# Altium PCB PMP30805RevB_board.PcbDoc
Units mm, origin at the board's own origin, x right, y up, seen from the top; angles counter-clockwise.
Board outline 68.58 x 25.4 mm, 2 copper layers (Top Layer, Bottom Layer), stack 1.575 mm thick; 47 components, 22 nets, 119 pads, 31 vias.
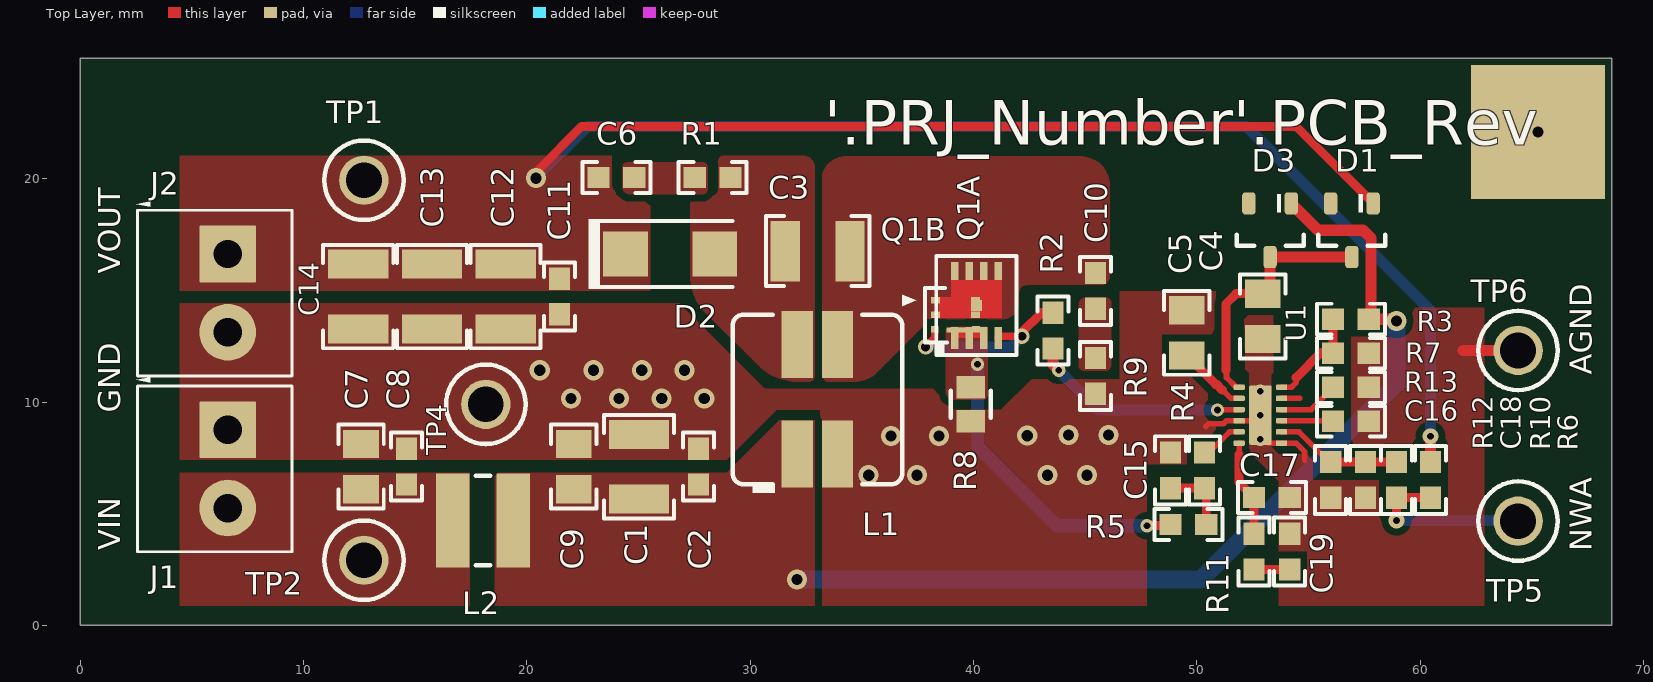
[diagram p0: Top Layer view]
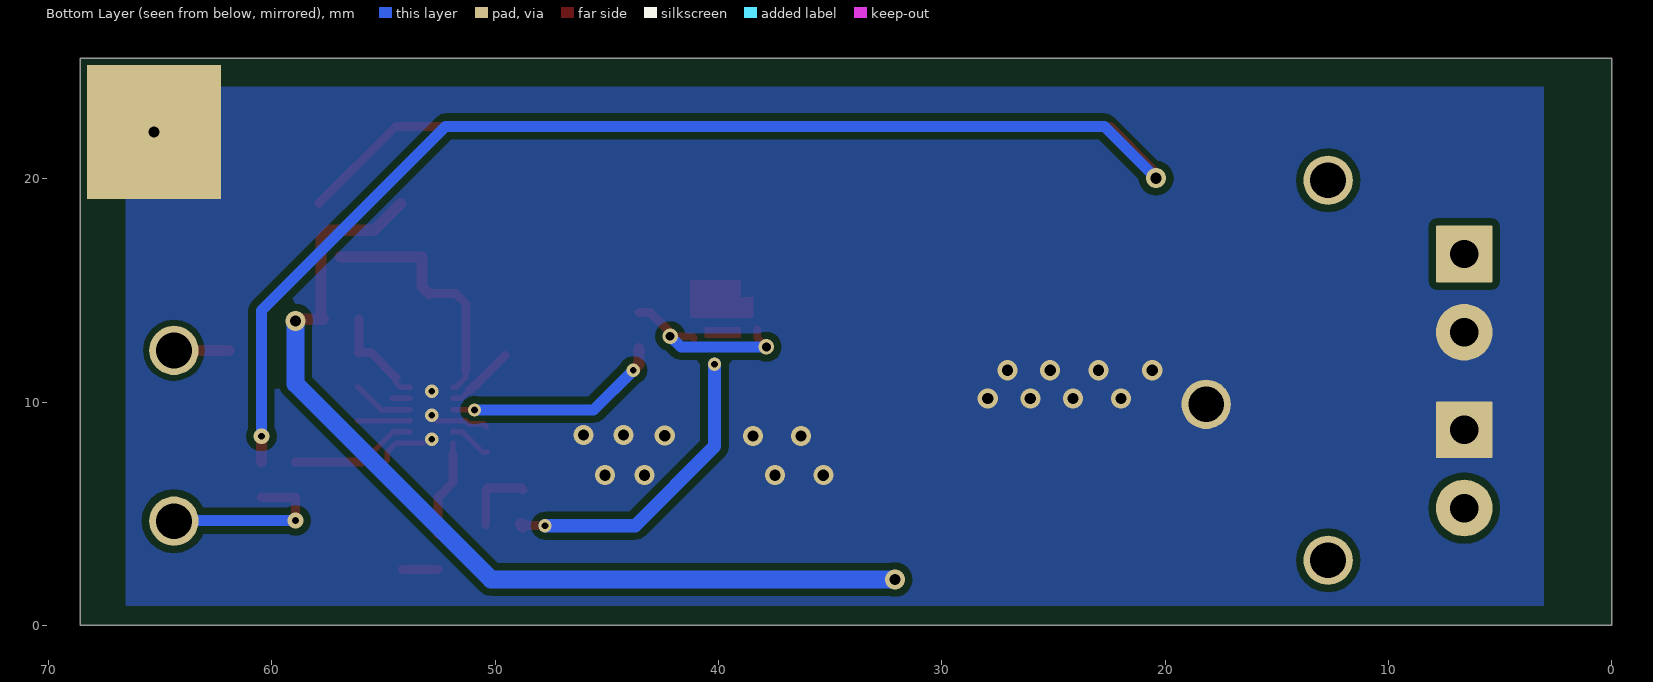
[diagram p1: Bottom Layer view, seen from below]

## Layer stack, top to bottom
Top Solder: solder mask 0.0102, Solder Resist, Dk 3.5
Top Layer: signal copper 0.0356
Dielectric1: core 1.5037, FR-4, Dk 4.8
Bottom Layer: signal copper 0.0356
Bottom Solder: solder mask 0.0102, Solder Resist, Dk 3.5

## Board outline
0,0 0,25.4 68.58,25.4 68.58,0

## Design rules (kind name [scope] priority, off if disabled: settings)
AcuteAngle [All] p1: minimum=4.50000000000000E+0001 checktracksonly=FALSE
AssemblyTestPointUsage [All] p1: valid=2
BoardOutlineClearance BoardOutlineClearance_MountingHoles [OnCopper and InComponentClass('Mounting Holes')] p1: gap=1 ignorepadtopadclearanceinfootprint=FALSE
BoardOutlineClearance BoardOutlineClearance_Poly [OnCopper and IsPoly] p2: gap=0.635 ignorepadtopadclearanceinfootprint=FALSE
BoardOutlineClearance [OnCopper and Not InComponentClass('Logo') and not InComponentClass('FiducialMark') and not InRegion(1000,500,4000,800) and not InPoly] p3: gap=1.905 ignorepadtopadclearanceinfootprint=FALSE
Clearance Clearance_Keepouts [((IsTrack Or IsArc) And Not InPoly) And IsFree and IsKeepOut vs ((IsTrack Or IsArc) And Not InPoly) And IsFree and IsKeepOut] p1: gap=0 ignorepadtopadclearanceinfootprint=FALSE
Clearance Clearance_Poly_1 [InPolygon vs InComponent('U1')] p2: gap=0.32 ignorepadtopadclearanceinfootprint=TRUE except(0.2: Arc-Fill Arc-Poly Arc-Region Track-Fill Track-Poly Track-Region SMDPad-Fill SMDPad-Poly SMDPad-Region Fill-Fill Fill-Poly Fill-Region Poly-Poly Poly-Region Region-Region)
Clearance Clearance_Poly [InPolygon] p3: gap=0.32 ignorepadtopadclearanceinfootprint=TRUE
Clearance Clearance_FiducialMark [IsKeepOut and InComponentClass('FiducialMark') vs IsPad and InComponentClass('FiducialMark')] p4: gap=0 ignorepadtopadclearanceinfootprint=FALSE
Clearance [All] p5: gap=0.2 ignorepadtopadclearanceinfootprint=TRUE
ComponentClearance ComponentClearance_MountingHoles_FiducialMarks [InComponentClass('Mounting Holes') vs InComponentClass('FiducialMark')] p1: gap=1.27 collisioncheckmode=3 verticalgap=0.254 showdistances=FALSE
ComponentClearance ComponentClearance_Shunt [InComponentClass('Header') vs InComponentClass('Shunt')] p2: gap=0 collisioncheckmode=3 verticalgap=0 showdistances=FALSE
ComponentClearance ComponentClearance_Logo [InComponentClass('Logo')] p3: gap=1.27 collisioncheckmode=3 verticalgap=0.254 showdistances=FALSE
ComponentClearance ComponentClearance_ScrewToNut [(HasFootprint('NY PMS 440 0025 PH')) vs (HasFootprint('Keystone_1902C'))] p4: gap=0.127 collisioncheckmode=3 verticalgap=0.254 showdistances=FALSE
ComponentClearance ComponentClearance_MountingHoles [InComponentClass('Mounting Holes')] p5: gap=6.35 collisioncheckmode=3 verticalgap=2540 showdistances=FALSE
ComponentClearance ComponentClearance_SmallPassives [HasFootprint('0201*') or HasFootprint('0402*') or HasFootprint('0508') or HasFootprint('0603*') or HasFootprint('0612') or HasFootprint('0805*') or HasFootprint('0815*') or HasFootprint('0830*') or HasFootprint('1206*') or HasFootprint('1210*') or HasFootprint('1808*') or HasFootprint('1812*') or HasFootprint('1825*') or HasFootprint('2010*') or HasFootprint('2220*') or HasFootprint('2225*') or HasFootprint('2512*') or HasFootprint('2728*') or HasFootprint('3518*') or HasFootprint('PG-TSDSON-8FL') vs HasFootprint('0201*') or HasFootprint('0402*') or HasFootprint('0508') or HasFootprint('0603*') or HasFootprint('0612') or HasFootprint('0805*') or HasFootprint('0815*') or HasFootprint('0830*') or HasFootprint('1206*') or HasFootprint('1210*') or HasFootprint('1808*') or HasFootprint('1812*') or HasFootprint('1825*') or HasFootprint('2010*') or HasFootprint('2220*') or HasFootprint('2225*') or HasFootprint('2512*') or HasFootprint('2728*') or HasFootprint('3518*') or HasFootprint('PG-TSDSON-8FL')] p6: gap=0.38 collisioncheckmode=3 verticalgap=0.254 showdistances=FALSE
ComponentClearance ComponentClearance_THtoSMT [IsThruComponent vs IsSMTComponent] p7: gap=1.016 collisioncheckmode=3 verticalgap=0.762 showdistances=FALSE
ComponentClearance ComponentClearance_THtoTH [IsThruComponent vs IsThruComponent] p8: gap=0.762 collisioncheckmode=3 verticalgap=0.762 showdistances=FALSE
ComponentClearance ComponentClearance_1 [InComponent('Q1A') vs InComponent('Q1B')] p9: gap=0 collisioncheckmode=3 verticalgap=0 showdistances=FALSE
ComponentClearance [All] p10: gap=0.762 collisioncheckmode=3 verticalgap=0.254 showdistances=FALSE
DiffPairsRouting [All] p1: maxlimit=2.54 minlimit=0.254 mostfreqgap=0.254 toplayer_minwidth=0.381 toplayer_maxwidth=0.381 toplayer_prefwidth=0.381 bottomlayer_minwidth=0.381 bottomlayer_maxwidth=0.381 bottomlayer_prefwidth=0.381 maxuncoupledlength=25.4
FabricationTestPointUsage TestPointUsage [All] p1: valid=2 allowmultiple=FALSE
FabricationTestpoint Testpoint [All] p1: side=3 testpointundercomponent=TRUE minsize=1.016 maxsize=2.54 preferedsize=1.524 minholesize=0 maxholesize=1.016 preferedholesize=0.813 testpointgrid=0.025 allowsidetop=TRUE allowsidebottom=TRUE usegrid=TRUE gridtolerance=0
FanoutControl Fanout_LCC [IsLCC] p1: bgadir=Out bgaviamode=Centered fanoutstyle=Auto fanoutdirection=Alternating viagrid=0.025 // Fanout_LCC (Default Rule)
FanoutControl Fanout_BGA [IsBGA] p2: bgadir=Out bgaviamode=Centered fanoutstyle=Auto fanoutdirection=Alternating viagrid=0.025 // Fanout_BGA (Default Rule)
FanoutControl Fanout_Default [All] p4: bgadir=Out bgaviamode=Centered fanoutstyle=Auto fanoutdirection=Alternating viagrid=0.025 // Fanout_Default (Default Rule)
FanoutControl Fanout_Small [(CompPinCount < 5)] p5: bgadir=Out bgaviamode=Centered fanoutstyle=Auto fanoutdirection=OutThenIn viagrid=0.025 // Fanout_Small (Default Rule)
HoleSize [All] p1: absolutevalues=TRUE maxlimit=6.375 minlimit=0.3 maxpercent=80.000 minpercent=20.000
MinimumAnnularRing MinimumAnnularRing_ThermalPadVias [IsVia and InAnyComponent] p1: minimumring=0.15
MinimumAnnularRing [All] p2: minimumring=0.2
MinimumSolderMaskSliver MinimumSolderMaskSliver_Logo [InComponentClass('Logo') vs InComponentClass('Logo')] p1: minsoldermaskwidth=0.018
MinimumSolderMaskSliver [All] p2: minsoldermaskwidth=0.1
PlaneConnect [All] p1: planeconnectstyle=Relief reliefexpansion=0.254 reliefentries=4 reliefconductorwidth=0.254 reliefairgap=0.254
PolygonConnect PolygonConnect_TP6 [InComponent('TP6')] p1: connectstyle=NoConnect reliefconductorwidth=0.254 reliefentries=4 polygonreliefangle="90 Angle" airgapwidth=0.254
PolygonConnect [All] p2: connectstyle=Direct reliefconductorwidth=0.254 reliefentries=4 polygonreliefangle="90 Angle" airgapwidth=0.254
RoutingVias ThermalPadVias [IsVia and InAnyComponent] p1: holewidth=0.2 width=0.5 viastyle="Through Hole" minholewidth=0.2 minwidth=0.5 maxholewidth=0.33 maxwidth=0.6
RoutingVias [All] p2: holewidth=0.5 width=0.9 viastyle="Through Hole" minholewidth=0.3 minwidth=0.6 maxholewidth=1.016 maxwidth=1.651
SilkToBoardRegionClearance [Not ((IsComment or IsDesignator) And (Hide <> 'False')) and not InRegion(1000,500,4000,800)] p1:
SilkToSilkClearance SilkToSilkClearance_Pb-FreeLogo [(HasFootprint('Pb-Free_Overlay_Medium') OR HasFootprint('Pb-Free_Overlay_Small')) vs (HasFootprint('Pb-Free_Overlay_Medium') OR HasFootprint('Pb-Free_Overlay_Small'))] p1: silktosilkclearance=0
SilkToSilkClearance [All] p2: silktosilkclearance=0.1
SilkToSolderMaskClearance SilkToComponentPadClearance [(IsPad or IsFill or IsRegion) and InAnycomponent] p1: minsilkscreentomaskgap=0.127 clearancetoexposedcopper=TRUE
SilkToSolderMaskClearance "Silk to Solder Mask Opening" [All] p2: minsilkscreentomaskgap=0.1 clearancetoexposedcopper=FALSE
SolderMaskExpansion [All] p1: expansion=0.05
UnRoutedNet [All] p1: checkbadconnections=TRUE
Width [All] p1: maxlimit=2.54 minlimit=0.152 preferedwidth=0.254 checkconnectedcopper=TRUE
14 further rules are at their usual default settings.

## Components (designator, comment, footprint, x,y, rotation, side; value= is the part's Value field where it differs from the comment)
C1 "GRM32ER71H106KA12L" 1210_270 25.019,7.112 r90 top value=10uF
C2 "GCM188R71H104KA57D" 0603 27.686,7.112 r90 top value=0.1uF
C3 "GRM32ER71H106KA12L" 1210_270 33.02,16.764 r0 top value=10uF
C4 "GRM21BR71H105KA12L" 0805_HV 52.959,13.843 r90 top value=1uF
C5 "GRM21BR71A105KA01L" 0805_HV 49.549,13.108 r90 top value=1uF
C6 "GCM1885C2A101JA16D" 0603 24.003,20.066 r180 top value=100pF
C7 "GRM21BR71H105KA12L" 0805_HV 12.573,7.112 r90 top value=1uF
C8 "GCM188R71H103KA37D" 0603 14.605,7.112 r90 top value=0.01uF
C9 "GRM21BR71H105KA12L" 0805_HV 22.098,7.112 r90 top value=1uF
C10 "GCM1885C2A101JA16D" 0603 45.466,14.986 r270 top value=100pF
C11 "GRM188R71E104KA01D" 0603 21.463,14.732 r270 top value=0.1uF
C12 "GRM32ER71E226KE15L" 1210_270 19.05,14.732 r270 top value=22uF
C13 "GRM32ER71E226KE15L" 1210_270 15.748,14.732 r270 top value=22uF
C14 "GRM32ER71E226KE15L" 1210_270 12.446,14.732 r270 top value=22uF
C15 "GRM188R71E102KA01D" 0603 48.824,6.951 r90 top value=1000pF
C16 "GRM188R71E104KA01D" 0603 56.896,9.144 r0 top value=0.1uF
C17 "GRM1885C1E561JA01D" 0603 53.358,5.733 r0 top value=560pF
C18 "GRM1885C1H220JA01D" 0603 57.554,6.524 r270 top value=22pF
C19 "GRM188R71E104KA01D" 0603 54.158,3.306 r90 top value=0.1uF
D1 "BAS16LT1G" SOT-23 56.945,17.7 r270 top value=100V
D2 "B360AM-13-F" SMA 26.416,16.637 r0 top value=60V
D3 "BAS16LT1G" SOT-23 53.281,17.7 r270 top value=100V
J1 "ED555/2DS" TERM_BLK_ED555-2DS 6.604,8.763 r270 top
J2 "ED555/2DS" TERM_BLK_ED555-2DS 6.604,16.637 r270 top
L1 "SRF0703-100M" SRF0703 33.009,10.123 r90 top value=10uH
L2 "SRN4012TA-R47M" SRN4012TA 18.034,4.699 r0 top value=470nH
Q1A "IAUZ18N10S5L420" PG-TSDSON-8FL 40.132,14.325 r90 top value=100V
Q1B "SQA442EJ-T1-GE3" PowerPAK_SC-70 39.192,13.894 r0 top value=60V
R1 "CRCW060310R0JNEAHP" 0603 28.321,20.066 r0 top value=10
R2 "ERJ-3GEY0R00V" 0603 43.561,13.208 r90 top value=0
R3 "CRCW0603261KFKEA" 0603 56.896,13.716 r0 top value=261k
R4 "ERJ-3GEY0R00V" 0603 50.348,6.951 r270 top value=0
R5 "CRCW0603100RFKEA" 0603 49.623,4.524 r180 top value=100
R6 "CRCW060349R9FKEA" 0603 60.468,6.524 r90 top value=49.9
R7 "CRCW060393K1FKEA" 0603 56.896,12.192 r180 top value=93.1k
R8 "WSLP0805R0300FEB" WSLP0805 39.878,9.906 r90 top value=0.03
R9 "CRCW060310R0JNEAHP" 0603 45.466,11.176 r90 top value=10
R10 "CRCW060360K4FKEA" 0603 58.944,6.524 r270 top value=60.4k
R11 "CRCW06033K32FKEA" 0603 52.558,3.306 r90 top value=3.32k
R12 "CRCW06035K49FKEA" 0603 55.995,6.524 r90 top value=5.49k
R13 "CRCW060310K0FKEA" 0603 56.896,10.668 r180 top value=10.0k
TP1 "5010" Keystone5010 12.7,19.939 r0 top
TP2 "5010" Keystone5010 12.7,2.921 r0 top
TP4 "5011" Keystone5011 18.161,9.906 r0 top
TP5 "5014" Keystone5014 64.389,4.674 r0 top
TP6 "5011" Keystone5011 64.389,12.319 r0 top
U1 "LM51551QDSSRQ1" DSS0012C 52.848,9.418 r0 top

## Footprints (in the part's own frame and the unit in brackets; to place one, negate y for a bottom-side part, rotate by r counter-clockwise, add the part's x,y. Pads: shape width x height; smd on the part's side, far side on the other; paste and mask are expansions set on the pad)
0603 [mm] "0603 from SM-752 data"
  rect 1x0.95 smd: 1(-0.8,0) 2(0.8,0)
  silkscreen extent -1.52,-0.69 1.52,0.69, body extent -0.87,-0.47 0.87,0.47, height 1
0805_HV [mil] "0805 with 30mil clearance between pads"
  rect 50x63 smd: 1(-40,0) 2(40,0)
  silkscreen extent -74,-40 74,40, body extent -43,-29 43,29, height 57
1210_270 [mm] "1210"
  rect 1.3x2.7 smd: 1(-1.45,0) 2(1.45,0)
  silkscreen extent -2.32,-1.57 2.32,1.57, body extent -1.7,-1.35 1.7,1.35, height 2.7
DSS0012C [mm] "WSON-12"
  rrect40% 0.5x0.25 smd: 1(-0.95,1.25) 2(-0.95,0.75) 3(-0.95,0.25) 4(-0.95,-0.25) 5(-0.95,-0.75) 6(-0.95,-1.25) 7(0.95,-1.25) 8(0.95,-0.75) 9(0.95,-0.25) 10(0.95,0.25) 11(0.95,0.75) 12(0.95,1.25)
  rrect11% 0.95x1.17 on Top Paste: 13(0,-0.685) 13(0,0.685)
  rrect11% 1x2.65 smd paste-0.5: 13(0,0)
  body extent -1,-1.5 1,1.5, height 0.81
Keystone5010 [mil] "Keystone Multipurpose loops"
  round 87 hole 63: 1(0,0)
  silkscreen extent -70,-70 70,70, body extent -63,-63 63,62, height 319
Keystone5011 [mil] "Keystone Multipurpose loops"
  round 87 hole 63: 1(0,0)
  silkscreen extent -70,-70 70,70, body extent -63,-63 63,62, height 319
Keystone5014 [mil] "Keystone Multipurpose loops"
  round 87 hole 63: 1(0,0)
  silkscreen extent -70,-70 70,70, body extent -63,-63 63,62, height 319
PG-TSDSON-8FL [mm] "SMD, 8-Leads, Body 3.3x3.3mm, Pitch 0.65mm"
  rect 1x0.34 smd: 1(-1.45,0.975) 2(-1.45,0.325) 3(-1.45,-0.325) 4(-1.45,-0.975)
  rect 0.8x0.34 smd: 5(1.55,-0.975) 6(1.55,-0.325) 7(1.55,0.325) 8(1.55,0.975)
  rect 0.5x0.5 smd: 9(0,0)
  Top Layer region: -0.56,-1.145 1.15,-1.145 1.15,1.145 -0.56,1.145
  Top Layer region: -0.95,1.15 -1.45,1.15 -1.45,-0.49 -0.95,-0.49
  silkscreen extent -2.22,-1.8 2.22,1.8, body extent -1.7,-1.7 1.7,1.7, height 1.11
PowerPAK_SC-70 [mm] "Vishay PowerPAK SC70-6L  document 73001 rev 06-Aug-07"
  rect 0.401x0.3 smd: 1(-0.9,0.666) 2(-0.9,0.016) 5(0.9,0.016) 6(0.9,0.666)
  rect 0.35x0.3 smd: 3(-0.925,-0.634) 4(0.925,-0.634)
  rect 0.87x0.235 smd: 7(0.04,-0.666)
  Top Layer region: 0.75,0.816 -0.75,0.816 -0.75,-0.134 0.75,-0.134
  silkscreen extent -2.39,-1.22 -0.38,1.22, body extent -1,-1 1.05,1.05, height 0.73
SMA [mm] "Molded Diode, 2-Leads, Body 4.3x2.6mm, IPC Medium Density, based on OnSemi component dimensions and land pattern"
  rect 2x2 smd: 1(-2,0) 2(2,0)
  silkscreen extent -3.66,-1.57 2.79,1.57, body extent -2.6,-1.3 2.6,1.3, height 2.42
SOT-23 [mm] "SOT23, 3-Leads, Body 2.9x1.3mm, Pitch 0.95mm, Lead Span 2.5mm, IPC Medium Density"
  rrect50% 1x0.6 smd: 1(-1.2,0.95) 2(-1.2,-0.95) 3(1.2,0)
  silkscreen extent -1.63,-1.5 0.7,1.5, body extent -1.16,-1.45 1.21,1.45, height 1
SRF0703 [mm] "SMD, 4-Leads, Body 7.6x7.6mm"
  rect 3x1.4 smd: 1(-2.45,0.9) 2(-2.45,-0.9) 3(2.45,-0.9) 4(2.45,0.9)
  silkscreen extent -4.2,-3.8 3.8,3.8, body extent -3.8,-3.8 3.8,3.8, height 3.41
SRN4012TA [mm] "SMD, 2-Leads, Body 4.2x4.2mm"
  rect 1.5x4.2 smd: 1(-1.35,0) 2(1.35,0)
  silkscreen extent -0.33,-2 0.33,2, body extent -1.99,-1.99 1.99,1.99, height 1.19
TERM_BLK_ED555-2DS [mil]
  rrect4% 100x100 hole 50: 1(0,0)
  round 100 hole 50: 2(138,0)
  silkscreen extent -93,-161 215,113, body extent -69,-150 207,106, height 323
WSLP0805 [mm] "Vishay"
  rect 1.02x1.27 smd: 1(-0.76,0) 2(0.76,0)
  silkscreen extent -0.6,-0.9 0.6,0.9, body extent -1.14,-0.76 1.14,0.76, height 0.64

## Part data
C1 C3: library part CMP-0009226-3, "CAP, CERM, 10 uF, 50 V, +/- 10%, X7R, 1210", Cap_Case=1210, Manufacturer=MuRata, Supplier Part Number 1=490-6544-1-ND, TempCo=X7R, Tolerance_%=10%, Value1=Unknown, Value2=50V, ValueDisplayed=10uF
C2: "CAP, CERM, 0.1 µF, 50 V,+/- 10%, X7R, 0603", Cap_Case=0603, Manufacturer=MuRata, Supplier Part Number 1=490-4779-1-ND, TempCo=X7R, Tolerance_%=10, Value1="0.02 ohm", Value2=50V, ValueDisplayed=0.1µF
C4: library part CMP-0008350-2, "CAP, CERM, 1 uF, 50 V, +/- 10%, X7R, 0805", Cap_Case=0805, Manufacturer=MuRata, Supplier Part Number 1=490-4736-1-ND, TempCo=X7R, Tolerance_%=10%, Value1=Unknown, Value2=50V, ValueDisplayed=1uF
C5: library part CMP-0008313-2, "CAP, CERM, 1 uF, 10 V, +/- 10%, X7R, 0805", Cap_Case=0805, Manufacturer=MuRata, Supplier Part Number 1=490-1695-1-ND, TempCo=X7R, Tolerance_%=10%, Value1="0.007 ohm", Value2=10V, ValueDisplayed=1uF
C6 C10: "CAP, CERM, 100 pF, 100 V,+/- 5%, C0G/NP0, AEC-Q200 Grade 1, 0603", Cap_Case=0603, Manufacturer=MuRata, Supplier Part Number 1=490-4771-1-ND, TempCo=C0G/NP0, Tolerance_%=5, Value2=100V, ValueDisplayed=100pF
C7 C9: "CAP, CERM, 1 µF, 50 V,+/- 10%, X7R, 0805", Cap_Case=0805, Manufacturer=MuRata, Supplier Part Number 1=490-4736-1-ND, TempCo=X7R, Tolerance_%=10, Value2=50V, ValueDisplayed=1µF
C8: "CAP, CERM, 0.01 µF, 50 V,+/- 10%, X7R, AEC-Q200 Grade 1, 0603", Cap_Case=0603, Manufacturer=MuRata, Supplier Part Number 1=490-4778-1-ND, TempCo=X7R, Tolerance_%=10, Value2=50V, ValueDisplayed=0.01µF
C11 C16 C19: "CAP, CERM, 0.1 µF, 25 V,+/- 10%, X7R, 0603", Cap_Case=0603, Manufacturer=MuRata, Supplier Part Number 1=490-1524-1-ND, TempCo=X7R, Tolerance_%=10, Value2=25V, ValueDisplayed=0.1µF
C12 C13 C14: "CAP, CERM, 22 µF, 25 V,+/- 10%, X7R, 1210", Cap_Case=1210, Manufacturer=MuRata, Supplier Part Number 1=490-5313-1-ND, TempCo=X7R, Tolerance_%=10, Value1="0.002334 ohm", Value2=25V, ValueDisplayed=22µF
C15: "CAP, CERM, 1000 pF, 25 V,+/- 10%, X7R, 0603", Cap_Case=0603, Manufacturer=MuRata, Supplier Part Number 1=GRM188R71E102KA01D-ND, TempCo=X7R, Tolerance_%=10, Value2=25V, ValueDisplayed=1000pF
C17: "CAP, CERM, 560 pF, 25 V,+/- 5%, C0G/NP0, 0603", Cap_Case=0603, Manufacturer=MuRata, Supplier Part Number 1=GRM1885C1E561JA01D-ND, TempCo=C0G/NP0, Tolerance_%=5, Value2=25V, ValueDisplayed=560pF
C18: "CAP, CERM, 22 pF, 50 V,+/- 5%, C0G/NP0, 0603", Cap_Case=0603, Manufacturer=MuRata, Supplier Part Number 1=490-1411-1-ND, TempCo=C0G/NP0, Tolerance_%=5, Value2=50V, ValueDisplayed=22pF
D1 D3: library part CMP-0029193-2, "Diode, Switching, 100 V, 0.2 A, SOT-23", Manufacturer="ON Semiconductor", Value1=0.2A, Value2=1.25V
D2: "Diode, Schottky, 60 V, 3 A, AEC-Q101, SMA", Manufacturer="Diodes Inc.", Supplier Part Number 1=B360AM-13-FDICT-ND, Value1=3A, Value2=0.7V
J1 J2: library part CMP-0074913-1, "Terminal Block, 3.5mm Pitch, 2x1, TH", Color=Grey, Current_A=6A, Manufacturer="On-Shore Technology", Supplier Part Number 1=ED1514-ND, Voltage_V=150V
L1: "Coupled inductor, 10 µH, 2.47 A, 0.1652 ohm, SMD", Manufacturer=Bourns, Supplier Part Number 1=SRF0703-100MCT-ND, ValueDisplayed=10µH
L2: "Inductor, Shielded, Ferrite, 470 nH, 3.2 A, 0.03 ohm, AEC-Q200 Grade 1, SMD", Manufacturer=Bourns, Supplier Part Number 1=SRN4012TA-R47MCT-ND, Value1="0.03 ohm", Value2=3.2A, ValueDisplayed=470nH
Q1A: library part BSZ013NE2LS5IATMA1, "MOSFET, N-CH, 100 V, 40 A, 8-PG-TSDSON", Alternate Manufacturer=None, Manufacturer="Infineon Technologies", Value1="0.055 ohm", Value2="5.4 nC"
Q1B: library part CMP-0000233-1, "MOSFET, N-CH, 20 V, 7.8 A, AEC-Q101, PowerPAK SC-70", Alternate Manufacturer=None, Manufacturer=Vishay-Siliconix, PartNumber=SQA442EJ-T1_GE3, Supplier Part Number 1=SQA442EJ-T1_GE3CT-ND, Value1=0.032, Value2="9.7 nC"
R1 R9: "RES, 10, 5%, 0.25 W, 0603", Manufacturer=Vishay-Dale, Power_W=0.25, Supplier Part Number 1=541-10SACT-ND, TempCo="200 ppm/C", Tolerance_%=5, Value1=5%, Value2=0.25W, Value_Code=10R0, ValueDisplayed=10
R2 R4: library part CMP-0025874-4, "RES, 0, 5%, 0.1 W, AEC-Q200 Grade 0, 0603", Manufacturer=Panasonic, Power_W=100mW, Supplier Part Number 1=P0.0GCT-ND, TempCo="600 ppm/C", Tolerance_%=5%, Value2=0.1W, Value_Code=0000, ValueDisplayed=0
R3: library part CMP-0022244-4, "RES, 261 k, 1%, 0.1 W, AEC-Q200 Grade 0, 0603", Manufacturer=Vishay-Dale, Power_W=100mW, Supplier Part Number 1=541-261KHCT-ND, TempCo="100 ppm/C", Tolerance_%=1%, Value2=0.1W, Value_Code=261k
R5: library part CMP-0021991-2, "RES, 100, 1%, 0.1 W, 0603", Manufacturer=Vishay-Dale, Power_W=100mW, Supplier Part Number 1=541-100HCT-ND, TempCo="100 ppm/C", Tolerance_%=1%, Value2=0.1W, Value_Code=100R, ValueDisplayed=100
R6: library part CMP-0022448-4, "RES, 49.9, 1%, 0.1 W, AEC-Q200 Grade 0, 0603", Manufacturer=Vishay-Dale, Power_W=100mW, Supplier Part Number 1=541-49.9HCT-ND, TempCo="100 ppm/C", Tolerance_%=1%, Value2=0.1W, Value_Code=49R9, ValueDisplayed=49.9
R7: library part CMP-0022655-4, "RES, 93.1 k, 1%, 0.1 W, AEC-Q200 Grade 0, 0603", Manufacturer=Vishay-Dale, Power_W=100mW, Supplier Part Number 1=541-93.1KHCT-ND, TempCo="100 ppm/C", Tolerance_%=1%, Value2=0.1W, Value_Code=93k1, ValueDisplayed=93.1k
R8: "RES, 0.03, 1%, 0.5 W, 0805", Manufacturer=Vishay-Dale, Power_W=0.5, Supplier Part Number 1=WSLPB-.03CT-ND, TempCo="75 ppm/C", Tolerance_%=1, Value1=1%, Value2=0.5W, Value_Code=R030, ValueDisplayed=0.03
R10: library part CMP-0022532-4, "RES, 60.4 k, 1%, 0.1 W, AEC-Q200 Grade 0, 0603", Manufacturer=Vishay-Dale, Power_W=100mW, Supplier Part Number 1=541-60.4KHCT-ND, TempCo="100 ppm/C", Tolerance_%=1%, Value2=0.1W, Value_Code=60k4, ValueDisplayed=60.4k
R11: "RES, 3.32 k, 1%, 0.1 W, 0603", Manufacturer=Vishay-Dale, Power_W=0.1, Supplier Part Number 1=541-3.32KHCT-ND, TempCo="100 ppm/C", Tolerance_%=1, Value1=1%, Value2=0.1W, Value_Code=3k32, ValueDisplayed=3.32k
R12: library part CMP-0022512-4, "RES, 5.49 k, 1%, 0.1 W, AEC-Q200 Grade 0, 0603", Manufacturer=Vishay-Dale, Power_W=100mW, Supplier Part Number 1=541-5.49KHCT-ND, TempCo="100 ppm/C", Tolerance_%=1%, Value2=0.1W, Value_Code=5k49, ValueDisplayed=5.49k
R13: "RES, 10.0 k, 1%, 0.1 W, 0603", Manufacturer=Vishay-Dale, Power_W=0.1, Supplier Part Number 1=541-10.0KHCT-ND, TempCo="100 ppm/C", Tolerance_%=1, Value1=1%, Value2=0.1W, Value_Code=10k0, ValueDisplayed=10.0k
TP1 TP2: library part CMP-0055147-1, "Test Point, Multipurpose, Red, TH", Color=Red, Manufacturer=Keystone, Supplier Part Number 1=36-5010-ND
TP4 TP6: library part CMP-0055148-1, "Test Point, Multipurpose, Black, TH", Color=Black, Manufacturer=Keystone, Supplier Part Number 1=36-5011-ND
TP5: library part CMP-0055151-1, "Test Point, Multipurpose, Yellow, TH", Color=Yellow, Manufacturer=Keystone, Supplier Part Number 1=36-5014-ND
U1: library part CMP-0081541-1, "Automotive Grade 2.2-MHz Wide Input Non-synchronous Boost Controller, DSS0012C (WSON-12)", Alternate Manufacturer="Texas Instruments", Alternate PartNumber=LM51551QDSSTQ1

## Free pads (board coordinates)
  rect 6x6 hole 0.5: 7(65.278,22.098)

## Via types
v1: diameter 0.9, hole 0.5, Top Layer to Bottom Layer, 17 vias
v2: diameter 0.6, hole 0.3, Top Layer to Bottom Layer, 6 vias
v3: diameter 0.9, hole 0.5, Top Layer to Bottom Layer, tented top, 3 vias
v4: diameter 0.7, hole 0.4, Top Layer to Bottom Layer, 2 vias
v5: diameter 0.7, hole 0.3, Top Layer to Bottom Layer, tented top, 2 vias
v6: diameter 0.6, hole 0.3, Top Layer to Bottom Layer, tented top, 1 vias

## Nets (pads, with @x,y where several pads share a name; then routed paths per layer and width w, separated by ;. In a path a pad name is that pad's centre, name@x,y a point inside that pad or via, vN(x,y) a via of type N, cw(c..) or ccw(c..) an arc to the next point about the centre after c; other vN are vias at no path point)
AGND: C1.2 C2.2 C4.1 C5.2 C7.2 C8.2 C9.2 C11.2 C12.2 C13.2 C14.2 C15.2 C16.2 C17.2 C18.2 C19.2 J1.1 J2.2 L1.2 pad.7 R7.1 R8.1 R9.1 R12.1 R13.1 TP4.1 TP6.1 U1.4 U1.7 U1.13@52.848,9.418 | length 7.3
  Top Layer w0.25: 50.394,8.906 50.515,9.027 51.186,9.027 51.327,9.168 U1.4 52.598,9.168 v2(52.848,9.418) ; U1.13@53.213,8.168 U1.7 54.447,8.168 54.827,7.787 54.827,7.41
  Top Layer w0.5: 61.935,12.319 TP6.1
  other v1: 37.465,6.731 43.307,6.731 45.085,6.731 38.461,8.481 42.406,8.501 44.252,8.534 46.051,8.534 21.971,10.16 24.13,10.16 26.035,10.16 27.94,10.16 20.574,11.43 22.987,11.43 25.146,11.43 27.051,11.43
  other v2: 52.848,8.343 52.848,10.493
  other v3: 35.306,6.731 36.309,8.481
NetC3_1: C3.1 D2.2 L1.4 R1.2
NetC3_2: C3.2 C10.1 L1.3 Q1A.5 Q1A.6 Q1A.7 Q1A.8 Q1A.9 Q1B.1 Q1B.2 Q1B.5 Q1B.6
NetC4_2: C4.2 D1.3 D3.3 U1.1 | length 11.3
  Top Layer w0.25: 51.308,11.43 51.329,11.409 51.329,11.104 51.765,10.668 U1.1
  Top Layer w0.4: 51.308,11.43 51.308,14.402 51.765,14.859 C4.2
  Top Layer w0.5: C4.2 53.281,15.181 D3.3 D1.3
NetC5_1: C5.1 U1.2 | length 3.1
  Top Layer w0.25: 51.148,10.543 51.523,10.168 U1.2
  Top Layer w0.4: C5.1 50.846,10.795 50.896,10.795 51.148,10.543
NetC6_1: C6.1 R1.1
NetC7_1: C7.1 C8.1 J1.2 L2.1 TP2.1
NetC10_2: C10.2 R9.2
NetC15_1: C15.1 R4.2 R5.1 | length 3.3
  Top Layer w0.4: C15.1@48.749,6.076 C15.1 R4.2 50.423,6.076 R5.1
NetC16_1: C16.1 U1.9 | length 2.3
  Top Layer w0.25: U1.9 C16.1@56.145,9.168
NetC17_1: C17.1 R11.2 U1.6 | length 4.3
  Top Layer w0.25: 51.898,7.662 U1.6
  Top Layer w0.4: 51.898,7.662 51.898,6.393 C17.1 R11.2
NetC19_1: C19.1 R11.1 | length 1.6
  Top Layer w0.4: R11.1 C19.1
NetQ1A_1: Q1A.1 Q1A.2 Q1A.3 Q1B.4 Q1B.7 R5.2 R8.2 | length 13.8
  Top Layer w0.4: v2(47.768,4.47) R5.2@48.769,4.47
  Top Layer w0.6: R5.2@48.769,4.47 R5.2
  Bottom Layer w0.6: v2(40.178,11.693) 40.178,8.02 43.728,4.47 v2(47.768,4.47)
NetQ1A_4: Q1A.4 Q1B.3 R2.2 | length 8.5
  Top Layer w0.34: v4(37.855,12.476) 38.267,12.888 Q1B.3 ; Q1A.4 41.186,12.954 v4(42.164,12.954)
  Top Layer w0.4: v4(42.164,12.954) 42.164,13.122 43.05,14.008 R2.2
  Bottom Layer w0.5: v4(37.855,12.476) 41.686,12.476 v4(42.164,12.954)
NetR2_1: R2.1 U1.3 | length 9.9
  Top Layer w0.25: v6(50.927,9.652) 50.943,9.668 U1.3
  Top Layer w0.5: R2.1 43.561,11.684 v2(43.815,11.43) v2@43.777,11.43
  Bottom Layer w0.5: v2(43.815,11.43) 45.593,9.652 v6(50.927,9.652)
NetR3_1: R3.1 R7.2 U1.12 | length 4.7
  Top Layer w0.25: U1.12 54.234,10.668 54.447,10.881 54.447,11.104
  Top Layer w0.4: 54.447,11.104 55.577,12.234 R7.2@56.096,12.234 ; R7.2 R7.2@56.096,12.234 ; R3.1 R7.2@56.096,12.234 ; R7.2@56.145,12.234 R7.2@56.096,12.234
NetR4_1: R4.1 U1.5 | length 1.9
  Top Layer w0.25: R4.1 50.546,7.751 51.463,8.668 U1.5
NetR6_1: R6.1 R10.2 TP5.1 | length 8
  Top Layer w0.4: v5(58.944,4.699) R10.2 R6.1
  Bottom Layer w0.5: v5(58.944,4.699) TP5.1@64.389,4.699
NetR13_2: R13.2 U1.10 | length 2.8
  Top Layer w0.25: U1.10 55.12,9.668 56.12,10.668 R13.2@56.145,10.668
VFB: C18.1 R10.1 R12.2 U1.8 | length 5.7
  Top Layer w0.25: U1.8 54.583,8.668 55.927,7.324 R12.2
  Top Layer w0.4: R12.2 C18.1 R10.1
VIN: C1.1 C2.1 C9.1 D3.1 L1.1 L2.2 R3.2 | length 42.4
  Top Layer w0.5: D3.1 55.431,17.7 57.445,17.7 57.795,17.35 R3.2@57.795,13.772 ; R3.2 58.864,13.716 v3(58.944,13.637)
  Bottom Layer w0.8: v1(32.099,2.057) 32.099,2.061 50.182,2.061 58.944,10.823 v3(58.944,13.637)
VOUT: C6.2 C11.1 C12.1 C13.1 C14.1 D1.1 D2.1 J2.1 R6.2 TP1.1 | length 94.5
  Top Layer w0.4: v1@20.512,20.398 22.466,22.352 54.407,22.352 ; 54.443,22.352 D1.1
  Top Layer w0.5: R6.2 v5(60.468,8.481)
  Bottom Layer w0.5: v1(20.4,20.032) 22.72,22.352 ; 26.416,22.352 22.72,22.352 ; 52.172,22.352 22.72,22.352 ; 52.218,22.352 60.468,14.102 v5(60.468,8.481)
pads on no net: D1.2 D3.2 U1.11 U1.13@52.848,8.733 U1.13@52.848,10.103
copper on no net: | length 0.8
  Top Layer w0.25: 53.798,10.168 54.618,10.168

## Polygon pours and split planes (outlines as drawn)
NetC6_1 on Top Layer "TOP_LAYER_NETC6_1_P003" (solid, remove dead copper, pour order 3): 28.089,19.554 28.089,20.51 ccw(c27.844,20.51) 27.844,20.754 24.521,20.754 ccw(c24.521,20.504) 24.271,20.504 24.271,19.659 ccw(c24.626,19.659) 24.626,19.304 27.839,19.304 ccw(c27.839,19.554)
NetC10_2 on Top Layer "TOP_LAYER_NETC10_2_P001" (solid, remove dead copper, pour order 1): 46.158,13.691 46.158,14.472 ccw(c45.949,14.472) 45.949,14.681 45.009,14.681 ccw(c45.009,14.376) 44.704,14.376 44.708,14.224 44.708,11.638 ccw(c44.934,11.638) 44.934,11.412 45.908,11.412 ccw(c45.908,11.662) 46.158,11.662
AGND on Top Layer "TOP_LAYER_AGND_P016" (solid, remove dead copper, pour order 16): 52.349,8.915 52.349,7.786 53.677,6.458 53.677,0.889 62.865,0.889 62.865,14.224 56.442,14.224 54.731,12.513 54.731,9.256 54.381,8.906
AGND on Top Layer "TOP_LAYER_AGND_P014" (solid, remove dead copper, pour order 14): 42.605,11.035 46.544,11.035 46.544,14.967 50.846,14.967 50.846,7.214 39.53,7.214 39.157,7.587 39.157,9.376 39.433,9.652 41.222,9.652
AGND on Top Layer "TOP_LAYER_AGND_P013" (solid, remove dead copper, pour order 13): 4.445,14.425 26.814,14.425 30.646,10.593 38.191,10.593 39.116,9.668 47.768,9.668 47.768,0.889 33.147,0.889 33.147,9.668 31.196,9.668 28.954,7.426 4.445,7.426
AGND on Top Layer "TOP_LAYER_AGND_P010" (solid, remove dead copper, pour order 10): 52.131,13.975 53.423,13.975 53.423,11.31 53.34,11.227 53.34,9.779 52.349,9.779 52.349,11.303 52.172,11.481 52.172,11.938
NetQ1A_1 on Top Layer "TOP_LAYER_NETQ1A_1_P009" (solid, remove dead copper, pour order 9): 40.622,13.375 38.9,13.375 ccw(c38.9,13.238) 38.763,13.238 38.763,10.456 ccw(c39.116,10.456) 39.116,10.103 40.4,10.103 ccw(c40.4,10.343) 40.64,10.343 40.64,13.357 ccw(c40.622,13.357)
NetC3_2 on Top Layer "TOP_LAYER_NETC3_2_P007" (solid, remove dead copper, pour order 7): 46.101,19.7 ccw(c44.793,19.7) 44.793,21.008 34.296,21.008 ccw(c34.296,19.902) 33.19,19.902 33.19,17.298 ccw(c33.204,17.285) 33.19,17.272 33.19,11.115 ccw(c33.384,11.115) 33.384,10.922 34.717,10.922 ccw(c34.717,12.223) 35.637,11.303 37.744,13.411 cw(c38.481,12.674) 38.481,13.716 41.273,13.716 ccw(c41.273,14.506) 41.832,13.947 ccw(c41.337,14.442) 42.037,14.442 42.037,14.901 cw(c42.376,14.901) 42.376,15.24 45.72,15.24 ccw(c45.72,15.621) 46.101,15.621
NetC3_1 on Top Layer "TOP_LAYER_NETC3_1_P006" (solid, remove dead copper, pour order 6): 27.305,18.8 cw(c27.739,18.8) 27.739,19.233 28.25,19.233 ccw(c28.25,19.558) 28.575,19.558 28.575,20.824 cw(c28.796,20.824) 28.796,21.045 32.354,21.045 cw(c32.354,20.51) 32.889,20.51 32.889,11.164 cw(c32.647,11.164) 32.647,10.922 32.127,10.922 cw(c32.127,13.462) 30.331,11.666 28.049,13.947 cw(c29.845,15.743) 27.305,15.743
VOUT on Top Layer "TOP_LAYER_VOUT_P005" (solid, remove dead copper, pour order 5): 25.519,17.35 25.519,18.804 ccw(c25.146,18.804) 25.146,19.177 24.511,19.177 cw(c24.441,19.812) 23.806,19.742 23.806,21.045 4.445,21.045 4.445,14.986 25.519,14.986
VIN on Top Layer "TOP_LAYER_VIN_P004" (solid, remove dead copper, pour order 4): 18.55,6.848 18.55,0.889 32.893,0.889 32.893,9.185 31.306,9.185 28.956,6.835
NetC7_1 on Top Layer "TOP_LAYER_NETC7_1_P002" (solid, remove dead copper, pour order 2): 4.445,6.835 4.445,0.889 17.45,0.889 17.45,6.835
AGND on Bottom Layer "BOTTOM_LAYER_AGND_P030" (solid, remove dead copper, pour order 30): 3.048,0.889 66.548,0.889 66.548,24.13 3.048,24.13

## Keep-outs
Keep-Out Layer:
  text ".Layer_Name" at 14.656,-23.076 h1.52

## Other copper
Top Layer:
  pour cut-out: 53.619,8.306 53.34,8.306 53.34,8.534
  pour cut-out: 53.287,8.052 53.677,7.662 54.611,7.662 54.221,8.052
  text ".Layer_Name" at 14.656,-23.076 h1.52
Bottom Layer:
  text ".Layer_Name" at 14.656,-23.076 h1.52

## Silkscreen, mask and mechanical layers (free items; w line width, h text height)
Top Overlay:
  text "'.PRJ_Number'.PCB_Rev" at 33.316,21.526 h2
  text "VOUT" at 1.778,15.748 h1 r90
  text "AGND" at 67.691,11.219 h1 r90
  text "GND" at 1.778,9.525 h1 r90
  text "VIN" at 1.778,3.378 h1 r90
  text "NWA" at 67.691,3.326 h1 r90
  text ".Layer_Name" at 14.656,-23.076 h1.52
Bottom Overlay:
  text ".Layer_Name" at 14.656,-23.076 h1.52
Top Paste:
  text ".Layer_Name" at 14.656,-23.076 h1.52
Bottom Paste:
  text ".Layer_Name" at 14.656,-23.076 h1.52
Top Solder:
  text ".Layer_Name" at 14.656,-23.076 h1.52
  text ".Layer_Name" at 14.656,-23.076 h1.52
Bottom Solder:
  text "'.PRJ_Number'.PCB_Rev" at 28.051,15.451 h2
  text ".Layer_Name" at 14.656,-23.076 h1.52
Drill Guide:
  text ".Layer_Name" at 14.656,-23.076 h1.52
M1 Board Outline:
  the board outline again, w0.254
  text ".Layer_Name" at 14.656,-23.076 h1.52
M2 Board Dimensions:
  rectangle: 0,-8.255 3.175,-5.08
  rectangle: 3.175,-11.43 12.7,-8.255
  lines w0.178: 0,-8.255 25.4,-8.255 ; 3.175,-11.43 3.175,-5.08 ; 6.35,-11.43 6.35,-5.08 ; 12.7,-11.43 12.7,-5.08 ; 19.05,-11.43 19.05,-5.08 ; 0,-11.43 25.4,-11.43 25.4,-5.08 0,-5.08 0,-11.43
  text "'.Print_Date' '.Print_Time'" at 1.778,26.67 h1.5
  text ".Layer_Name" at 14.656,-23.076 h1.52
M3 3D STEP Top:
  text ".Layer_Name" at 14.656,-23.076 h1.52
M4 3D STEP Bottom:
  text ".Layer_Name" at 14.656,-23.076 h1.52
M5 Assembly Top:
  lines w0.254: -7.417,-24.896 160.223,-24.896 ; -7.417,-19.732 160.274,-19.732 ; -7.417,-14.567 -7.417,-30.061 94.31,-30.061 160.274,-30.061 160.274,-14.567 -7.404,-14.567 -7.404,-30.061 32.614,-30.061 ; 55.194,-30.061 55.194,-14.567 ; 87.376,-19.732 87.376,-14.567 ; 108.712,-19.732 108.712,-14.567 ; 124.511,-30.226 124.511,-25.074
  text "COMPONENTS MARKED 'DNP' SHOULD NOT BE POPULATED." at 29.299,-9.36 h1.52
  text "ASSEMBLY VARIANT:" at 29.286,-12.294 h1.52
  text ".VariantName" at 55.601,-12.294 h1.52
  text "PCB VIEWED FROM TOP SIDE" at -5.804,-17.924 h1.52
  text "BOARD #:" at 57.099,-17.924 h1.52
  text ".PRJ_Number" at 70.955,-17.924 h1.52
  text "REV:" at 92.405,-17.924 h1.52
  text ".PCB_Rev" at 99.809,-17.924 h1.52
  text "SVN REV:" at 113.69,-17.924 h1.52
  text ".VersionControl_RevNumber" at 126.543,-17.924 h1.52
  text "TID #:" at 57.099,-23.089 h1.52
  text ".TID" at 70.955,-23.089 h1.52
  text "PLOT NAME =" at -5.804,-28.304 h1.52
  text ".plot_File_Name" at 14.656,-28.304 h1.52
  text "GENERATED    :" at 57.15,-28.304 h1.52
  text ".Print_Date" at 79.235,-28.304 h1.52
  text ".Print_Time" at 97.752,-28.304 h1.52
  text "TEXAS INSTRUMENTS" at 129.87,-28.304 h1.52
M6 Assembly Bottom:
  lines w0.254: -7.429,-19.744 160.261,-19.744 ; -7.379,-24.909 160.261,-24.909 ; 28.334,-30.239 28.334,-25.087 ; 44.133,-19.744 44.133,-14.58 ; 65.468,-19.744 65.468,-14.58 ; 97.65,-30.074 97.65,-14.58 ; 120.231,-30.074 160.249,-30.074 160.249,-14.58 -7.429,-14.58 -7.429,-30.074 58.534,-30.074 160.261,-30.074 160.261,-14.58
  text "COMPONENTS MARKED 'DNP' SHOULD NOT BE POPULATED." at 154.991,-9.347 h1.52
  text ".VariantName" at 128.473,-12.294 h1.52
  text "ASSEMBLY VARIANT:" at 154.864,-12.294 h1.52
  text ".VersionControl_RevNumber" at 26.302,-17.937 h1.52
  text "SVN REV:" at 39.154,-17.937 h1.52
  text ".PCB_Rev" at 53.035,-17.937 h1.52
  text "REV:" at 60.439,-17.937 h1.52
  text ".PRJ_Number" at 81.89,-17.937 h1.52
  text "BOARD #:" at 95.745,-17.937 h1.52
  text "PCB VIEWED FROM BOTTOM SIDE" at 158.648,-17.937 h1.52
  text ".TID" at 81.89,-23.101 h1.52
  text "TID #:" at 95.745,-23.101 h1.52
  text "TEXAS INSTRUMENTS" at 22.974,-28.317 h1.52
  text ".Print_Time" at 55.093,-28.317 h1.52
  text ".Print_Date" at 73.609,-28.317 h1.52
  text "GENERATED    :" at 95.694,-28.317 h1.52
  text ".plot_File_Name" at 138.189,-28.317 h1.52
  text "PLOT NAME =" at 158.648,-28.317 h1.52
M9 Title Sheet:
  drawing of 57 lines, arcs and shapes, not listed
  text "1" at 18.792,202.857 h1.78
  text "2" at 82.182,202.857 h1.78
  text "3" at 145.411,202.857 h1.78
  text "4" at 209.08,202.857 h1.78
  text "5" at 272.555,202.857 h1.78
  text "6" at 336.182,202.857 h1.78
  text "A" at -10.579,173.825 h1.78
  text "A" at 365.341,173.825 h1.78
  text "B" at -10.579,113.373 h1.78
  text "B" at 365.341,113.373 h1.78
  text "C" at -10.579,53.048 h1.78
  text "C" at 365.341,53.048 h1.78
  text "PROJECT TITLE:" at 288.125,5.779 h1.14
  text ".PRJ_Title" at 289.395,2.392 h1.78
  text "DESIGNED FOR:" at 288.125,-1.867 h1.14
  text ".PRJ_Customer" at 289.395,-5.423 h1.78
  text "D" at -10.579,-7.15 h1.78
  text "D" at 365.341,-7.15 h1.78
  text "FILE NAME:" at 288.125,-9.487 h1.14
  text ".PCB_File_Name_No_Path" at 289.395,-12.535 h1.78
  text "Texas Instruments (TI) and/or its licensors do not warrant the accuracy or completeness of this specification" at 161.9,-16.646 h1.14
  text "ENGINEER:" at 288.125,-16.853 h1.14
  text "LAYOUT BY:" at 326.352,-16.853 h1.14
  text "or any information contained therein. TI and/or its licensors do not warrant that this design will meet" at 160.757,-19.507 h1.14
  text ".PRJ_Engineer" at 289.395,-20.79 h1.78
  text ".PCB_Layout" at 327.635,-20.79 h1.78
  text "the specifications, will be suitable for your application or fit for any particular purpose, or will operate in" at 160.757,-22.369 h1.14
  text ".Layer_Name" at 14.656,-23.076 h1.52
  text "ALTIUM DESIGNER VERSION:" at 326.352,-24.727 h1.14
  text "an implementation. TI and/or its licensors do not warrant that the design is production worthy. You should" at 160.757,-25.231 h1.14
  text "completely validate and test your design implementation to confirm the system functionality for your application." at 161.9,-28.092 h1.14
  text ".print_Scale" at 289.395,-28.113 h1.78
  text ".Application_BuildNumber" at 327.635,-28.113 h1.78
  text "1" at 18.792,-33.363 h1.78
  text "2" at 82.182,-33.363 h1.78
  text "3" at 145.411,-33.363 h1.78
  text "4" at 209.08,-33.363 h1.78
  text "5" at 272.555,-33.363 h1.78
  text "6" at 336.182,-33.363 h1.78
M10 Fab Notes:
  drawing of 189 lines, arcs and shapes, not listed
  text "DESIGN INFORMATION" at 314.503,160.177 h1.52
  text "MIN. TRACK WIDTH:" at 298.131,156.821 h1.52
  text "8" at 325.976,156.821 h1.52
  text "MIL" at 329.907,156.821 h1.52
  text "MIN. CLEARANCE:" at 298.131,153.668 h1.52
  text "0.2" at 324.452,153.668 h1.52
  text "mm" at 329.907,153.668 h1.52
  text "MIN. VIA PAD SIZE:" at 298.131,150.515 h1.52
  text "24" at 325.214,150.515 h1.52
  text "MIL" at 329.907,150.515 h1.52
  text "0.05mm (2MIL)" at 315.784,147.216 h1.52
  text "MINIMUM ANNULAR RING" at 289.769,147.007 h1.52
  text "EXTERNAL" at 333.768,147.007 h1.52
  text "PER" at 294.849,144.21 h1.52
  text "IPC-D-275 CLASS 2 LEVEL C" at 300.437,144.21 h1.52
  text "MIL, HOLES" at 338.238,141.658 h1.52
  text "+/-" at 328.27,141.439 h1.52
  text "+/-" at 349.961,141.439 h1.52
  text "REGISTRATION TOLERANCES:" at 289.769,141.412 h1.52
  text "METAL" at 320.243,141.412 h1.52
  text "5" at 334.879,141.413 h1.52
  text "3" at 356.037,141.413 h1.52
  text "MIL" at 358.99,141.412 h1.52
  text "HOLE SIZE TOLERANCE (UNLESS OTHERWISE SPECIFIED):" at 289.769,138.915 h1.52
  text "+/-" at 349.961,138.842 h1.52
  text "3" at 356.037,138.815 h1.52
  text "MIL" at 358.99,138.815 h1.52
  text "MATERIAL:" at 287.87,135.319 h1.52
  text "FR-4 High Tg" at 312.926,132.054 h1.52
  text "X" at 309.257,131.852 h1.52
  text "FR-408" at 298.563,131.737 h1.52
  text "OTHER" at 336.358,131.737 h1.52
  text "62 MIL (1.6mm) +/-10%" at 306.694,128.104 h1.52
  text "X" at 303.643,128.042 h1.52
  text "THICKNESS:" at 289.769,127.895 h1.52
  text "OTHER" at 339.33,127.895 h1.52
  text "TOLERANCE:" at 289.769,124.382 h1.52
  text "X" at 311.314,124.382 h1.52
  text "ANSI IPC-6012 TYPE 3 CLASS 2" at 315.836,124.382 h1.52
  text "OTHER +/-" at 315.835,120.719 h1.52
  text "BOW & TWIST:" at 289.769,117.032 h1.52
  text "X" at 311.314,117.032 h1.52
  text "ANSI IPC-6012 TYPE 3 CLASS 2" at 315.836,117.032 h1.52
  text "OTHER +/-" at 315.835,113.306 h1.52
  text "DRILLING:" at 287.87,109.988 h1.52
  text "NC_DRILL FILES" at 332.599,107.316 h1.52
  text "REFERENCE:" at 289.769,107.216 h1.52
  text "X" at 306.463,107.214 h1.52
  text "AS SHOWN" at 310.984,107.216 h1.52
  text "X" at 329.348,107.216 h1.52
  text "OTHER" at 340.168,103.603 h1.52
  text "PTH COPPER THICKNESS:" at 289.761,103.513 h1.52
  text "X" at 318.697,103.513 h1.52
  text "20-30 um" at 321.948,103.513 h1.52
  text "BOARD FINISH:" at 287.87,99.764 h1.52
  text "SILKSCREEN:" at 291.812,96.967 h1.52
  text "X" at 316.14,96.967 h1.52
  text "TOP" at 319.112,96.967 h1.52
  text "X" at 329.094,96.967 h1.52
  text "BOTTOM" at 332.091,96.967 h1.52
  text "SILKSCREEN COLOR:" at 291.812,93.025 h1.52
  text "X" at 316.115,93.025 h1.52
  text "WHITE" at 319.112,93.025 h1.52
  text "OTHER" at 332.091,93.025 h1.52
  text "X" at 319.442,89.382 h1.52
  text "GREEN" at 322.439,89.382 h1.52
  text "OTHER" at 338.136,89.382 h1.52
  text "SOLDER RESIST COLOR:" at 291.812,89.207 h1.52
  text "X" at 319.442,85.464 h1.52
  text "MATTE" at 322.439,85.464 h1.52
  text "SEMI-GLOSS" at 338.125,85.447 h1.52
  text "IMMERSION GOLD (ENIG)" at 314.819,81.075 h1.52
  text "ENEPIG" at 348.793,80.892 h1.52
  text "SURFACE FINISH:" at 287.87,80.866 h1.52
  text "X" at 310.298,80.866 h1.52
  text "IMM. TIN/SILVER OR EQUIV" at 296.24,77.379 h1.52
  text "OTHER" at 332.599,77.279 h1.52
  text "ARRAY/PANEL:" at 287.87,73.332 h1.52
  text "CUT AND TRIM PER M1 BOARD OUTLINE" at 314.819,73.123 h1.52
  text "N.C. ROUTE" at 314.819,69.67 h1.52
  text "X" at 332.295,69.67 h1.52
  text "V. SCORE" at 336.816,69.67 h1.52
  text "CERTIFICATION:" at 287.87,66.39 h1.52
  text "MATERIALS AND WORKMANSHIP FOR ALL PCBS" at 306.285,66.39 h1.52
  text "TO MEET OR EXCEED THE REQUIREMENTS OF:" at 306.285,64.001 h1.52
  text "X" at 297.078,60.733 h1.52
  text "ANSI IPC-A-600F CLASS ->" at 300.329,60.733 h1.52
  text "X" at 342.188,60.733 h1.52
  text "2" at 344.982,60.733 h1.52
  text "1" at 336.981,60.695 h1.52
  text "3" at 353.973,60.695 h1.52
  text "X" at 317.702,56.982 h1.52
  text "RoHS" at 320.953,56.982 h1.52
  text "OTHER" at 337.321,56.982 h1.52
  text "PER ORDER" at 347.407,56.982 h1.52
  text "ALL BOARDS MUST MEET OR EXCEED UL94-V0 REQUIREMENTS." at 288.569,53.075 h1.52
  text "PCB MUST BEAR THE UL94V-0 UL REGISTERED MATERIAL ID NUMBER" at 288.569,50.127 h1.52
  text "ADDITIONAL REQUIREMENTS:" at 287.87,45.824 h1.52
  text "MICROSECTION:" at 289.769,43.103 h1.52
  text "YES" at 312.775,43.103 h1.52
  text "REQUIRED" at 334.657,39.437 h1.52
  text "BARE BOARD ELEC. TEST:" at 289.769,39.364 h1.52
  text "NONE" at 322.935,39.364 h1.52
  text "X" at 331.66,39.364 h1.52
  text "PER ORDER" at 349.693,39.364 h1.52
  text "XX MIL VIAS REQUIRE NON-CONDUCTIVE FILL AND PLANARIZE" at 294.04,34.158 h1.5
  text "XX MIL VIAS REQUIRE CONDUCTIVE FILL AND PLANARIZE" at 294.243,31.517 h1.52
  text "OUTER XX MIL TRACES REQUIRE 50 OHM SINGLE-ENDED IMPEDANCE" at 294.218,27.367 h1.47
  text "LAYER 2 & 3 (INNER LAYERS) XX MIL WIDE, XX MIL SPACE / TRACES REQUIRE 100 OHM DIFFERENTIAL IMPEDANCE" at 294.015,21.38 h1.52
  text ".Layer_Name" at 14.656,-23.076 h1.52
M11 Gerber Information:
  lines w0.254: -7.417,-24.896 160.223,-24.896 ; -7.417,-19.732 160.274,-19.732 ; -7.417,-14.567 -7.417,-30.061 94.31,-30.061 160.274,-30.061 160.274,-14.567 -7.404,-14.567 -7.404,-30.061 32.614,-30.061 ; 55.194,-30.061 55.194,-14.567 ; 87.376,-19.732 87.376,-14.567 ; 108.712,-19.732 108.712,-14.567 ; 124.511,-30.226 124.511,-25.074
  text "ALL ARTWORK VIEWED FROM TOP SIDE" at -5.804,-17.924 h1.52
  text "BOARD #:" at 57.099,-17.924 h1.52
  text ".PRJ_Number" at 70.955,-17.924 h1.52
  text "REV:" at 92.405,-17.924 h1.52
  text ".PCB_Rev" at 99.809,-17.924 h1.52
  text "SVN REV:" at 113.69,-17.924 h1.52
  text ".VersionControl_RevNumber" at 126.543,-17.924 h1.52
  text "LAYER NAME =" at -5.804,-23.076 h1.52
  text "TID #:" at 57.099,-23.089 h1.52
  text ".TID" at 70.955,-23.089 h1.52
  text "PLOT NAME =" at -5.804,-28.304 h1.52
  text ".plot_File_Name" at 14.656,-28.304 h1.52
  text "GENERATED    :" at 57.15,-28.304 h1.52
  text ".Print_Date" at 79.235,-28.304 h1.52
  text ".Print_Time" at 97.752,-28.304 h1.52
  text "TEXAS INSTRUMENTS" at 129.87,-28.304 h1.52
M12 Stackup:
  drawing of 191 lines, arcs and shapes, not listed
  text "Layer" at 249.119,186.182 h1.52
  text "Name" at 259.531,186.182 h1.52
  text "Material" at 283.147,186.182 h1.52
  text "Thickness" at 304.985,186.182 h1.52
  text "Constant" at 321.49,186.182 h1.52
  text "Board Layer Stack" at 335.965,186.182 h1.52
  text "Top Overlay" at 259.531,183.134 h1.52
  text "Top Solder" at 259.531,180.086 h1.52
  text "Solder Resist" at 283.147,180.086 h1.52
  text "0.40mil" at 304.985,180.086 h1.52
  text "3.5" at 321.49,180.086 h1.52
  text "1" at 249.119,177.038 h1.52
  text "Top Layer" at 259.531,177.038 h1.52
  text "Copper" at 283.147,177.038 h1.52
  text "1.40mil" at 304.985,177.038 h1.52
  text "Dielectric1" at 259.531,173.99 h1.52
  text "FR-4" at 283.147,173.99 h1.52
  text "59.20mil" at 304.985,173.99 h1.52
  text "4.8" at 321.49,173.99 h1.52
  text "2" at 249.119,170.942 h1.52
  text "Bottom Layer" at 259.531,170.942 h1.52
  text "Copper" at 283.147,170.942 h1.52
  text "1.40mil" at 304.985,170.942 h1.52
  text "Bottom Solder" at 259.531,167.894 h1.52
  text "Solder Resist" at 283.147,167.894 h1.52
  text "0.40mil" at 304.985,167.894 h1.52
  text "3.5" at 321.49,167.894 h1.52
  text "Bottom Overlay" at 259.531,164.846 h1.52
  text ".Layer_Name" at 14.656,-23.076 h1.52
M13 Component Bodies Top:
  text ".Layer_Name" at 14.656,-23.076 h1.52
M14 Component Bodies Bottom:
  text ".Layer_Name" at 14.656,-23.076 h1.52
M15 Courtyards Top:
  text ".Layer_Name" at 14.656,-23.076 h1.52
M16 Courtyards Bottom:
  text ".Layer_Name" at 14.656,-23.076 h1.52
Drill Drawing:
  circle w0.254: c136.241,75.248 r0.703
  lines w0.254: 135.538,71.383 136.944,71.383 136.944,72.788 135.538,72.788 135.538,71.383 ; 135.538,77.707 136.241,78.059 136.944,77.707 136.593,78.41 136.944,79.113 136.241,78.762 135.538,79.113 135.89,78.41 135.538,77.707 ; 135.538,82.275 136.944,82.275 136.241,80.87 135.538,82.275 ; 135.538,84.383 135.89,84.383 136.241,84.032 136.593,84.383 136.944,84.383 136.593,84.735 136.944,85.086 136.593,85.086 136.241,85.438 135.89,85.086 135.538,85.086 135.89,84.735 135.538,84.383
  lines w0.305: 134.264,70.434 216.362,70.434 ; 134.264,86.246 216.362,86.246 ; 142.85,67.272 142.85,89.408 ; 151.287,67.272 151.287,89.408 ; 167.453,67.272 167.453,89.408 ; 174.037,67.272 174.037,89.408 ; 183.568,67.272 183.568,89.408 ; 201.972,67.272 201.972,89.408 ; 134.264,67.272 216.362,67.272 216.362,89.408 134.264,89.408 134.264,67.272
  text "Symbol" at 136.162,87.194 h1.83
  text "Quantity" at 143.799,87.194 h1.83
  text "Finished Hole Size" at 152.235,87.194 h1.83
  text "Plated" at 168.402,87.194 h1.83
  text "Hole Type" at 174.986,87.194 h1.83
  text "Drill Layer Pair" at 184.517,87.194 h1.83
  text "Hole Tolerance" at 202.92,87.194 h1.83
  text "9" at 143.799,84.032 h1.52
  text "11.81mil (0.300mm)" at 152.235,84.032 h1.52
  text "PTH" at 168.402,84.032 h1.52
  text "Round" at 174.986,84.032 h1.52
  text "Top Layer - Bottom Layer" at 184.517,84.032 h1.52
  text "2" at 143.799,80.87 h1.52
  text "15.75mil (0.400mm)" at 152.235,80.87 h1.52
  text "PTH" at 168.402,80.87 h1.52
  text "Round" at 174.986,80.87 h1.52
  text "Top Layer - Bottom Layer" at 184.517,80.87 h1.52
  text "21" at 143.799,77.707 h1.52
  text "19.69mil (0.500mm)" at 152.235,77.707 h1.52
  text "PTH" at 168.402,77.707 h1.52
  text "Round" at 174.986,77.707 h1.52
  text "Top Layer - Bottom Layer" at 184.517,77.707 h1.52
  text "4" at 143.799,74.545 h1.52
  text "50.00mil (1.270mm)" at 152.235,74.545 h1.52
  text "PTH" at 168.402,74.545 h1.52
  text "Round" at 174.986,74.545 h1.52
  text "Top Layer - Bottom Layer" at 184.517,74.545 h1.52
  text "5" at 143.799,71.383 h1.52
  text "63.00mil (1.600mm)" at 152.235,71.383 h1.52
  text "PTH" at 168.402,71.383 h1.52
  text "Round" at 174.986,71.383 h1.52
  text "Top Layer - Bottom Layer" at 184.517,71.383 h1.52
  text "41 Total" at 143.799,68.221 h1.52
  text ".Layer_Name" at 14.656,-23.076 h1.52
M17 Embedded Cavity:
  text ".Layer_Name" at 14.656,-23.076 h1.52
M18 Embedded Assembly:
  text ".Layer_Name" at 14.656,-23.076 h1.52
M19 Embedded Keepout:
  text ".Layer_Name" at 14.656,-23.076 h1.52

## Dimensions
0,-11.43 to 25.4,-11.43 on M2 Board Dimensions
0,25.4 to 0,0 on M2 Board Dimensions
0,0 to 68.58,25.4 on M2 Board Dimensions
